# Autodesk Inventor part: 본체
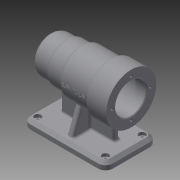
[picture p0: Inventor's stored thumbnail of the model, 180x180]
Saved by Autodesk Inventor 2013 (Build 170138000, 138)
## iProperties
Created: 2016-06
Part Number: 본체
Material: Generic
Document SubType Name: Modeling
Designer: Administrator
Density: 1 g/cm^3
Author: Administrator
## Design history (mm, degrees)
sketch "스케치1"
  geometry: L1 (0, 0)-(25, 0); L2 (25, 0)-(25, 25); L3 (25, 25)-(0, 25); L4 (0, 25)-(0, 0); L5 (25, 0)-(45, 0); L6 (45, 0)-(45, 27); L7 (45, 27)-(25, 27); L8 (25, 27)-(25, 0); L9 (45, 0)-(84, 0); L10 (84, 0)-(84, 30); L11 (84, 30)-(45, 30); L12 (45, 30)-(45, 0); L13 (84, 0)-(112, 0); L14 (112, 0)-(112, 34); L15 (112, 34)-(84, 34); L16 (84, 34)-(84, 0)
  constraints: 32 end point, 8 parallel, 4 horizontal, 4 perpendicular
  dimensions: "d0" = 25 distance of L2.end L3.end; "d2" = 45 distance between parallel lines of L6 L4; "d3" = 84 distance between parallel lines of L10 L4; "d4" = 112 distance between parallel lines of L14 L4; "d5" = 25 distance of L3.end L1.start; "d6" = 27 distance of L7.end L1.end; "d7" = 30 distance of L11.end L5.end; "d8" = 34 distance of L13.end L14.end
revolve "회전1" sketch "스케치1" stored, may be unused: angle "d9" = 90 deg
sketch "스케치2"
  geometry: L1 (0, -25)-(0, 25) reference; L2 (0, 25)-(25, 25) reference; L3 (25, 25)-(25, 27) reference; L4 (25, 27)-(45, 27) reference; L5 (45, 27)-(45, 30) reference; L6 (45, 30)-(84, 30) reference; L7 (84, 30)-(84, 34) reference; L8 (84, 34)-(112, 34) reference; L9 (112, 34)-(112, -34) reference; L10 (112, -34)-(84, -34) reference; L11 (84, -34)-(84, -30) reference; L12 (84, -30)-(45, -30) reference; L13 (45, -30)-(45, -27) reference; L14 (45, -27)-(25, -27) reference; L15 (25, -27)-(25, -25) reference; L16 (25, -25)-(0, -25) reference; L17 (112, -34)-(112, 34) reference; L18 (112, 0)-(97, 0); L19 (97, 0)-(97, 21); L20 (97, 21)-(112, 21); L21 (112, 21)-(112, 0); L22 (97, 0)-(43, 0); L23 (43, 0)-(43, 21); L24 (46, 24)-(94, 24); L25 (97, 21)-(97, 0); L26 (43, 0)-(31, 0); L27 (31, 0)-(31, 20.7); L28 (31.3, 21)-(43, 21); L29 (43, 21)-(43, 0); L30 (31, 0)-(13, 0); L31 (13, 0)-(13, 17.2); L32 (13.3, 17.5)-(31, 17.5); L33 (31, 17.5)-(31, 0); L34 (13, 0)-(9, 0); L35 (9, 0)-(9, 15.7); L36 (9.3, 16)-(13, 16); L37 (13, 16)-(13, 0); L38 (9, 0)-(6, 0); L39 (6, 0)-(6, 7.5); L40 (9, 10.5)-(9, 10.5); L41 (9, 10.5)-(9, 0); A1 r 0.3 centre (9.3, 15.7) between (9.3, 16) and (9, 15.7); A2 r 0.3 centre (13.3, 17.2) between (13.3, 17.5) and (13, 17.2); A3 r 0.3 centre (31.3, 20.7) between (31.3, 21) and (31, 20.7); A4 r 3 centre (9, 7.5) between (9, 10.5) and (6, 7.5); A5 r 3 centre (46, 21) between (46, 24) and (43, 21); A6 r 3 centre (94, 21) between (97, 21) and (94, 24); 7 further points
  constraints: 48 end point, 12 parallel, 12 point on circle, 12 point on line, 12 tangent, 6 centre point, 6 horizontal, 6 perpendicular, 3 equal radius, 1 midpoint
  dimensions: "d10" = 15 distance of L19.end L20.end; "d13" = 12 distance of point (31, 21) L28.end; "d14" = 18 distance of point (13, 17.5) L32.end; "d15" = 4 distance of point (9, 16) L36.end; "d16" = 3 distance of point (6, 10.5) L40.end; "d17" = 54 distance of point (43, 24) point (97, 24); "d18" = 21 distance between parallel lines of L18 L20; "d19" = 24 distance between parallel lines of L22 L24; "d20" = 21 distance between parallel lines of L26 L28; "d21" = 17.5 distance between parallel lines of L30 L32; "d22" = 16 distance between parallel lines of L34 L36; "d23" = 10.5 distance between parallel lines of L38 L40; "d24" = 0.3 radius of A1; "d25" = 3 radius of A4; "d27" = 3 radius of A5
revolve "회전2" sketch "스케치2" stored, may be unused: angle "d26" = 90 deg
node "작업 평면1"
sketch "스케치3"
  geometry: L1 (-112, 34)-(-112, -34) reference; L2 (-10, -35)-(-102, -35); L3 (-112, -25)-(-112, 25); L4 (-102, 35)-(-10, 35); L5 (0, 25)-(0, -25); A1 r 10 centre (-10, -25) between (-10, -35) and (0, -25); A2 r 10 centre (-10, 25) between (0, 25) and (-10, 35); A3 r 10 centre (-102, 25) between (-102, 35) and (-112, 25); A4 r 10 centre (-102, -25) between (-112, -25) and (-102, -35); 5 further points
  constraints: 9 point on line, 8 end point, 8 point on circle, 8 tangent, 4 centre point, 3 equal radius, 2 parallel, 1 horizontal, 1 perpendicular
  dimensions: "d29" = 112 distance of point (0, -35) point (-112, -35); "d31" = 70 distance of point (0, 35) point (0, -35); "d32" = 35 distance from line of point (0, 0) L4; "d33" = 10 radius of A1
extrude "돌출1" join sketch "스케치3" distance "d34" = 10; taper "d35" = 0 deg
sketch "스케치4"
  geometry: L1 (0, 25)-(0, -25) reference; L2 (10, -35)-(102, -35) reference; L3 (112, -25)-(112, 25) reference; L4 (52, 28)-(60, 28); L5 (60, 28)-(60, -28); L6 (60, -28)-(52, -28); L7 (52, -28)-(52, 28); L8 (52, 28)-(60, -28); L9 (60, 28)-(52, -28); L10 (20, 4)-(92, 4); L11 (92, 4)-(92, -4); L12 (92, -4)-(20, -4); L13 (20, -4)-(20, 4); L14 (20, 4)-(92, -4); L15 (92, 4)-(20, -4); 5 further points
  constraints: 24 end point, 7 midpoint, 4 parallel, 2 horizontal, 2 perpendicular, 1 horizontal alignment
  dimensions: "d36" = 56 distance from line of L3 point (56, 0); "d37" = 8 distance of L10.end L11.end; "d38" = 8 distance of L5.end L6.end; "d39" = 7 distance between parallel lines of L2 L6; "d40" = 20 distance between parallel lines of L13 L1
extrude "돌출2" join sketch "스케치4" stored distance "d41" = 10; taper "d42" = 0 deg
feature "면 기울기1" dims angle "d43" = 20 deg
sketch "스케치5"
  geometry: A1 r 10 centre (10, -25) between (0, -25) and (10, -35) reference; A2 r 10 centre (102, -25) between (102, -35) and (112, -25) reference; A3 r 10 centre (102, 25) between (112, 25) and (102, 35) reference; A4 r 10 centre (10, 25) between (10, 35) and (0, 25) reference; 5 further points
  constraints: 4 coincident
hole "구멍1" sketch "스케치5" at (10, 25), (10, -25), (102, -25), (102, 25) diameter "d44" = 5; stored, may be unused: countersink angle "d48" = 90 deg, drill point angle "d50" = 118 deg; dims "d45" = 6, "d46" = 9, "d47" = 4, "d49" = 8
sketch "스케치6"
  geometry: C1 r 21 at (0, 0) reference; 4 further points
  constraints: 1 vertical alignment, 5 other
  dimensions: "d51" = 26 distance of C1.centre point (0, 26); "d54" = 360 deg dimension on C1.centre point (0, 26) (derived)
hole "구멍2" sketch "스케치6" at (0, 26), (-26, 0), (0, -26), (26, 0) diameter "d56" = 3.242; stored, may be unused: countersink angle "d60" = 90 deg, drill point angle "d62" = 118 deg; dims "d57" = 8, "d58" = 9, "d59" = 4, "d61" = 11
fillet "모깎기1" dims "d63" = 10
fillet "모깎기2" dims "d64" = 3
fillet "모깎기3" dims "d65" = 3
fillet "모깎기4" dims "d66" = 3
fillet "모깎기5" dims "d67" = 3
chamfer "모따기1" distance "d68" = 4; stored, may be unused: second distance "d69" = 2, angle "d70" = 45 deg
chamfer "모따기2" distance "d74" = 1; stored, may be unused: second distance "d75" = 2, angle "d76" = 45 deg
node "작업 평면2"
sketch "스케치7"
  geometry: L1 (47.5, -34)-(47.5, 34) reference; 2 further points
  constraints: 1 horizontal alignment, 1 other
  dimensions: "d71" = 48 distance from line of L1 point (-0.5, 0)
feature "엠보싱1" sketch "스케치7" dims "d72" = 0.5, "d73" = 0
node "솔리드1"
node "절단 모서리 투영1"
